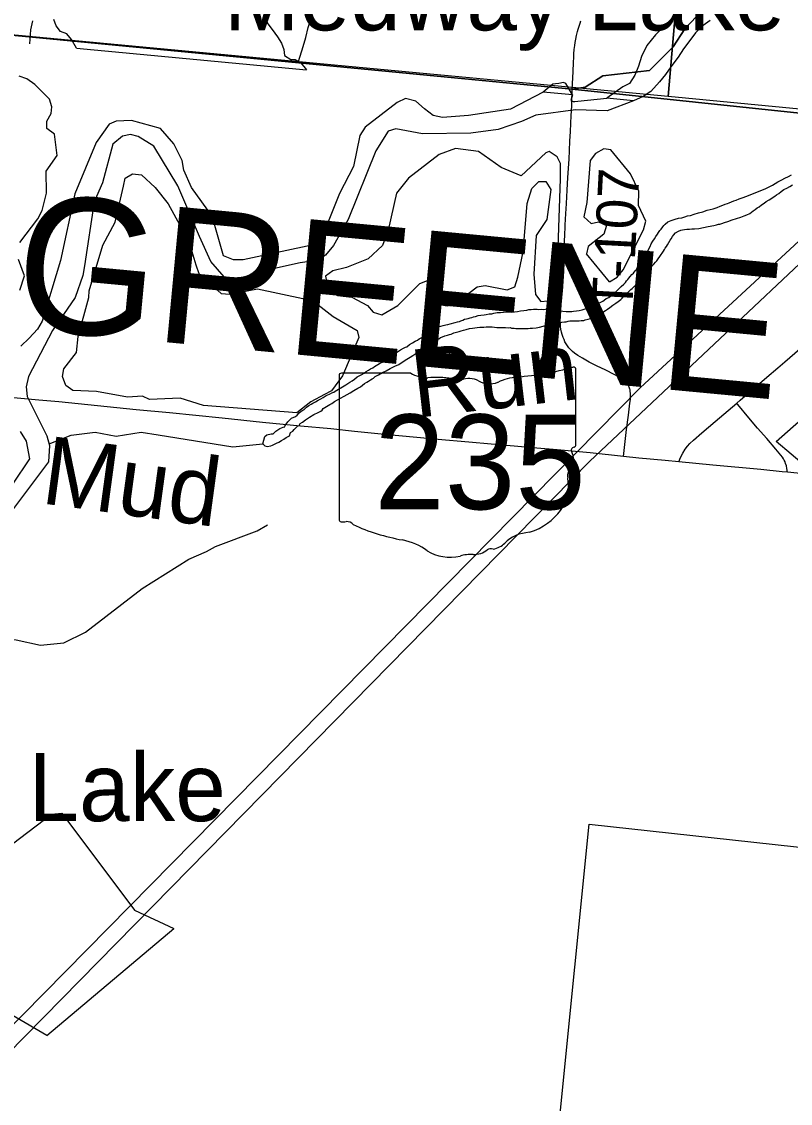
# Model space of a CAD drawing. Extents: x 0 to 1134, y 0 to 440.
# Drawn here: x 180.08 to 212.17, y 41.38 to 86.55 of the extents above; entities that cross this region are included whole.
import ezdxf

# ---------------------------------------------------------------- set-up
doc = ezdxf.new("R2010")
doc.units = 0
for name, color, linetype in [('GM_X_County_Road', 7, 'Continuous'), ('GM_X_County_Text', 7, 'Continuous'), ('GM_X_Major_River', 7, 'Continuous'), ('GM_X_Major_River_Text', 7, 'Continuous'), ('GM_X_Minor_Lake', 7, 'Continuous'), ('GM_X_Minor_Lake_Text', 7, 'Continuous'), ('GM_X_Minor_River', 7, 'Continuous'), ('GM_X_Rail_Line', 7, 'Continuous'), ('GM_X_Section', 7, 'Continuous'), ('GM_X_State_Location', 7, 'Continuous'), ('GM_X_State_Route', 7, 'Continuous'), ('GM_X_State_Shield', 7, 'Continuous'), ('GM_X_Township', 7, 'Continuous'), ('GM_X_Township_Road', 7, 'Continuous'), ('GM_X_Township_Road_Text', 7, 'Continuous'), ('GM_X_Unincorporated', 7, 'Continuous'), ('SH_Cut_Line', 7, 'Continuous')]:
    doc.layers.add(name, color=color, linetype=linetype)

msp = doc.modelspace()

# ---------------------------------------------------------------- linework, layer by layer
at = {"layer": 'GM_X_County_Road'}
msp.add_lwpolyline([(203.063, 83.709), (203.096, 84.469), (203.113, 84.838), (203.126, 85.062), (203.136, 85.208), (203.149, 85.388), (203.166, 85.548), (203.184, 85.681), (203.208, 85.815), (203.24, 85.969), (203.282, 86.14), (203.309, 86.23), (203.333, 86.318), (203.391, 86.486), (203.429, 86.579)], dxfattribs=at)
at = {"layer": 'GM_X_Major_River'}
for p, q in [((203.08, 83.489), (201.856, 83.604)), ((205.625, 83.249), (204.501, 83.355))]:
    msp.add_line(p, q, dxfattribs=at)
for points in [[(211.62, 91.109), (211.191, 90.801), (210.749, 90.459), (210.331, 90.128), (210.095, 89.826), (209.823, 89.411), (209.712, 89.095), (209.635, 88.778), (209.489, 88.383), (209.163, 88.106), (208.78, 87.831), (208.454, 87.566), (208.084, 87.324), (207.701, 87.072), (207.281, 86.672), (206.885, 86.329), (206.535, 85.996), (206.182, 85.549), (205.954, 85.088), (205.83, 84.692), (205.683, 84.32), (205.458, 83.961), (205.17, 83.832), (204.501, 83.355)], [(208.828, 86.599), (208.527, 86.39), (208.211, 86.079), (207.975, 85.766), (207.705, 85.42), (207.479, 85.072), (207.184, 84.669), (206.96, 84.345), (206.712, 84.032), (206.338, 83.631), (206.025, 83.423), (205.625, 83.249)], [(201.856, 83.604), (200.487, 82.899), (198.739, 82.627), (197.645, 82.554), (197.261, 82.632), (196.892, 82.915), (196.536, 83.231), (196.107, 83.345), (195.75, 83.173), (194.415, 82.14), (194.19, 81.793), (193.93, 80.504), (193.343, 79.371), (192.626, 77.57), (192.391, 77.258), (189.325, 76.601), (188.927, 76.6), (188.51, 76.77), (188.029, 78.432), (187.172, 79.627), (186.85, 80.352), (186.78, 80.752), (186.434, 81.444), (185.87, 82.084), (184.661, 82.424), (184.023, 82.395), (183.736, 82.267), (183.193, 81.508), (182.296, 79.36), (181.702, 76.578), (180.932, 74.04), (180.741, 73.704), (180.39, 73.326), (180.041, 72.995)], [(203.08, 83.489), (202.793, 83.971), (202.703, 84.008), (202.508, 83.967), (202.371, 83.959), (202.257, 83.94), (201.856, 83.604)], [(205.625, 83.249), (204.524, 82.825), (203.194, 82.872), (201.55, 82.643), (200.94, 82.386), (199.965, 82.048), (198.834, 81.896), (196.808, 81.859), (195.699, 82.071), (195.378, 81.977), (194.868, 81.161), (193.703, 78.292), (193.095, 77.205), (192.766, 76.793), (192.477, 76.619), (192.099, 76.538), (191.711, 76.48), (190.636, 76.247), (189.235, 75.739), (188.848, 75.738), (188.533, 75.894), (187.969, 76.535), (187.496, 77.582), (186.594, 79.688), (185.601, 81.352), (184.94, 81.757), (184.623, 81.833), (184.281, 81.774), (183.885, 81.432), (183.457, 79.818), (183.107, 79.02), (182.697, 76.347), (182.63, 75.95), (182.311, 75.026), (181.366, 73.653), (180.361, 71.735), (180.259, 71.294), (180.305, 70.895), (181.128, 69.258), (181.243, 68.856), (181.203, 68.164), (179.695, 66.168)], [(203.08, 83.489), (203.009, 83.261), (203.098, 83.213), (203.167, 83.211), (203.292, 83.231), (204.501, 83.355)], [(180.018, 69.435), (180.269, 69.031), (180.409, 68.287), (179.689, 67.238)]]:
    msp.add_lwpolyline(points, dxfattribs=at)
at = {"layer": 'GM_X_Minor_Lake'}
msp.add_line((182.362, 85.444), (191.964, 84.538), dxfattribs=at)
for points in [[(182.362, 85.444), (182.164, 85.804), (181.963, 86.046), (181.702, 86.141), (181.524, 86.382), (181.425, 86.645)], [(190.207, 86.703), (190.351, 86.462), (190.53, 86.22), (190.765, 85.921), (190.931, 85.657), (191.018, 85.394), (191.049, 85.132)], [(191.049, 85.132), (191.32, 84.968), (191.49, 84.966), (191.738, 84.826), (191.964, 84.538)], [(179.999, 77.333), (180.747, 78.319), (180.936, 78.669), (181.109, 79.382), (181.105, 80.305), (181.562, 80.967), (181.454, 81.846), (181.129, 82.092), (181.124, 82.4), (181.312, 82.715), (181.341, 82.999), (181.233, 83.309), (180.631, 83.924), (180.294, 84.159), (179.967, 84.28)], [(200.926, 80.106), (200.102, 80.453), (199.148, 81.133), (198.195, 81.255), (197.507, 81.007), (196.224, 80.02), (195.722, 79.392), (195.372, 77.839), (195.143, 77.195), (194.54, 76.649), (193.645, 76.28), (193.062, 76.144), (192.762, 75.922), (192.886, 75.316), (193.258, 75.115), (193.86, 75.046), (194.513, 74.702), (194.746, 74.413), (195.108, 74.303), (195.776, 74.699), (196.705, 75.614), (197.015, 75.745), (197.308, 75.625), (197.541, 75.313), (197.518, 74.732), (197.847, 74.68), (198.167, 74.765), (199.092, 75.475), (199.423, 75.525), (200.341, 75.347), (200.662, 75.477), (200.796, 75.884), (201.01, 76.939), (201.176, 78.951), (201.37, 79.585), (201.672, 79.875), (201.957, 79.881), (202.166, 79.546), (202.005, 78.285), (201.559, 77.623), (201.458, 76.008), (201.532, 75.152), (201.754, 74.863), (202.039, 74.891), (202.307, 75.205), (202.482, 77.126), (202.573, 79.982), (202.58, 80.301), (202.575, 80.62), (202.432, 80.907), (202.095, 81.13), (201.958, 81.065)], [(201.958, 81.065), (200.926, 80.106)], [(204.615, 75.682), (204.938, 75.88), (205.194, 76.182), (206.036, 77.851), (206.134, 78.224), (205.829, 78.868), (205.841, 79.472), (205.491, 80.196), (204.68, 81.192), (204.385, 81.243), (204.028, 81.046), (203.806, 80.754), (203.669, 78.992), (203.543, 78.402), (203.856, 78.123), (204.165, 78.185), (204.492, 78.041), (204.382, 77.679), (203.723, 77.157), (203.66, 76.851)], [(187.669, 70.514), (186.697, 70.83), (185.421, 70.765), (185.117, 70.908), (184.49, 70.875), (183.209, 71.106), (182.219, 71.149), (181.928, 71.36), (181.776, 71.728), (181.839, 72.057), (182.365, 72.729), (182.435, 73.4), (182.877, 75.03), (182.894, 75.315), (183.467, 77.216), (183.987, 78.174), (184.336, 79.681), (184.399, 80.01), (184.699, 80.197), (185.074, 80.155), (185.655, 79.62), (186.188, 78.948), (187.055, 77.371), (187.354, 76.397), (187.472, 76.03), (188.412, 75.202), (188.764, 75.172), (189.929, 75.388), (191.81, 74.985), (192.453, 74.721), (193.081, 74.23), (194.082, 73.652), (194.156, 73.366), (193.475, 71.763), (193.019, 71.134), (192.72, 70.981), (192.155, 70.667), (191.567, 70.218)], [(204.615, 75.682), (203.66, 76.851)], [(180.004, 75.34), (180.198, 75.939), (179.95, 76.616)], [(191.567, 70.218), (187.669, 70.514)], [(179.69, 52.215), (181.319, 53.458), (181.752, 53.494), (184.79, 49.446), (186.436, 48.683)], [(181.123, 44.212), (186.436, 48.683)], [(181.123, 44.212), (179.728, 45.026)]]:
    msp.add_lwpolyline(points, dxfattribs=at)
at = {"layer": 'GM_X_Minor_River'}
for points in [[(180.418, 85.628), (180.464, 86.215), (180.549, 86.59)], [(191.638, 84.883), (191.828, 85.508), (191.935, 85.882), (192.044, 86.302), (192.163, 86.698)], [(209.706, 79.023), (209.809, 79.067), (209.912, 79.1), (210.027, 79.144), (210.153, 79.199), (210.347, 79.264), (210.519, 79.329), (211.046, 79.537), (211.15, 79.581), (211.253, 79.636), (211.345, 79.68), (211.425, 79.725), (211.54, 79.791), (211.644, 79.858), (211.816, 79.946), (211.942, 80.013), (212.091, 80.079), (212.218, 80.156)], [(210.622, 78.644), (210.703, 78.711), (210.784, 78.778), (210.864, 78.822), (210.968, 78.9), (211.072, 78.967), (211.164, 79.034), (211.279, 79.112), (211.52, 79.256), (211.589, 79.312), (211.682, 79.379), (211.785, 79.457), (211.9, 79.535), (212.027, 79.601), (212.142, 79.668), (212.257, 79.734)], [(200.294, 74.425), (200.408, 74.435), (200.522, 74.421), (200.659, 74.43), (200.785, 74.451), (200.91, 74.472), (201.036, 74.481), (201.161, 74.502), (201.253, 74.523), (201.344, 74.533), (201.447, 74.543), (201.538, 74.542), (201.606, 74.54), (201.674, 74.528), (201.765, 74.538), (201.879, 74.536), (201.948, 74.546), (202.039, 74.556), (202.096, 74.555), (202.187, 74.542), (202.255, 74.541), (202.312, 74.529), (202.38, 74.517), (202.437, 74.504), (202.516, 74.469), (202.675, 74.455), (202.812, 74.441), (202.948, 74.45), (203.051, 74.449), (203.119, 74.459), (203.245, 74.468), (203.348, 74.489), (203.473, 74.522), (203.599, 74.554), (203.737, 74.609), (203.84, 74.652), (203.92, 74.685), (203.989, 74.718), (204.115, 74.785), (204.172, 74.795), (204.253, 74.839), (204.345, 74.884), (204.402, 74.917), (204.483, 74.984), (204.586, 75.028), (204.678, 75.095), (204.759, 75.15), (204.84, 75.229), (204.921, 75.307), (205.002, 75.397), (205.106, 75.486), (205.221, 75.587), (205.291, 75.654), (205.326, 75.722), (205.384, 75.778), (205.43, 75.834), (205.488, 75.902), (205.558, 75.992), (205.616, 76.048), (205.686, 76.138), (205.744, 76.205), (205.86, 76.374), (205.919, 76.487), (206, 76.577), (206.047, 76.667), (206.105, 76.769), (206.164, 76.859), (206.199, 76.938), (206.246, 77.04), (206.317, 77.164), (206.364, 77.277), (206.423, 77.379), (206.493, 77.48), (206.551, 77.571), (206.621, 77.672), (206.668, 77.751), (206.726, 77.83), (206.772, 77.886), (206.842, 77.976), (206.888, 78.032), (206.946, 78.088), (207.05, 78.189), (207.199, 78.244), (207.36, 78.298), (207.497, 78.341), (207.634, 78.362), (207.76, 78.394), (207.874, 78.438), (208, 78.459), (208.16, 78.513), (208.332, 78.567), (208.515, 78.61), (208.698, 78.675), (208.95, 78.739), (209.11, 78.794), (209.236, 78.849), (209.35, 78.881), (209.454, 78.925), (209.545, 78.958), (209.614, 78.979), (209.706, 79.023)], [(200.705, 73.735), (200.83, 73.733), (200.978, 73.742), (201.092, 73.729), (201.217, 73.738), (201.309, 73.748), (201.4, 73.746), (201.56, 73.766), (201.697, 73.787), (201.845, 73.83), (201.983, 73.874), (202.131, 73.905), (202.28, 73.937), (202.417, 73.969), (202.531, 73.979), (202.634, 74), (202.737, 74.021), (202.805, 74.02), (202.896, 74.041), (202.965, 74.051), (203.022, 74.062), (203.352, 74.056), (203.432, 74.067), (203.546, 74.076), (203.603, 74.098), (203.729, 74.119), (203.821, 74.151), (203.878, 74.162), (203.958, 74.195), (204.039, 74.25), (204.165, 74.305), (204.245, 74.361), (204.337, 74.416), (204.452, 74.483), (204.533, 74.55), (204.637, 74.617), (204.763, 74.706), (204.89, 74.795), (204.982, 74.862), (205.086, 74.94), (205.167, 75.018), (205.225, 75.108), (205.294, 75.164), (205.352, 75.209), (205.41, 75.265), (205.514, 75.366), (205.572, 75.41), (205.653, 75.489), (205.745, 75.567), (205.815, 75.657), (205.85, 75.714), (205.896, 75.77), (205.931, 75.838), (206.001, 75.916), (206.07, 75.983), (206.175, 76.096), (206.233, 76.174), (206.303, 76.264), (206.383, 76.343), (206.464, 76.421), (206.545, 76.5), (206.592, 76.567), (206.65, 76.646), (206.72, 76.736), (206.872, 76.962), (206.918, 77.041), (206.942, 77.097), (207, 77.165), (207.047, 77.232), (207.094, 77.323), (207.152, 77.424), (207.187, 77.481), (207.246, 77.582), (207.292, 77.638), (207.373, 77.728), (207.5, 77.806), (207.592, 77.839), (207.672, 77.86), (207.751, 77.87), (207.854, 77.88), (207.957, 77.89), (208.059, 77.899), (208.173, 77.898), (208.344, 77.918), (208.538, 77.949), (208.733, 77.991), (208.973, 78.044), (209.087, 78.065), (209.167, 78.087), (209.224, 78.086), (209.304, 78.119), (209.419, 78.162), (209.556, 78.206), (209.739, 78.271), (209.923, 78.336), (210.106, 78.39), (210.243, 78.434), (210.358, 78.477), (210.472, 78.533), (210.542, 78.6), (210.622, 78.644)], [(190.14, 68.916), (190.236, 69.222), (190.317, 69.301), (190.488, 69.332), (190.579, 69.342), (190.695, 69.454), (190.856, 69.565), (190.994, 69.62), (191.062, 69.63), (191.074, 69.687), (191.191, 69.833), (191.341, 69.99), (191.513, 70.067), (191.582, 70.123), (191.664, 70.213), (191.744, 70.28), (191.813, 70.324), (191.871, 70.358), (191.963, 70.447), (192.067, 70.514), (192.159, 70.57), (192.228, 70.614), (192.343, 70.68), (192.458, 70.747), (192.561, 70.802), (192.665, 70.858), (192.791, 70.935), (192.929, 70.99), (193.021, 71.045), (193.112, 71.078), (193.17, 71.123), (193.239, 71.167), (193.538, 71.345), (193.607, 71.378), (193.699, 71.445), (193.779, 71.5), (193.871, 71.556), (193.975, 71.622), (194.09, 71.712), (194.274, 71.811), (194.377, 71.866), (194.458, 71.934), (194.562, 71.989), (194.642, 72.056), (194.734, 72.1), (194.815, 72.144), (194.884, 72.189), (195.01, 72.278), (195.125, 72.333), (195.194, 72.389), (195.298, 72.433), (195.39, 72.488), (195.482, 72.566), (195.586, 72.644), (195.724, 72.733), (195.896, 72.844), (196.023, 72.911), (196.103, 72.955), (196.16, 72.977), (196.276, 73.066), (196.39, 73.133), (196.506, 73.21), (196.597, 73.255), (196.678, 73.299), (196.758, 73.343), (196.838, 73.376), (196.919, 73.454), (197, 73.521), (197.081, 73.589), (197.184, 73.644), (197.288, 73.699), (197.391, 73.754), (197.472, 73.799), (197.575, 73.831), (197.678, 73.864), (197.78, 73.885), (197.872, 73.906), (197.963, 73.927), (198.18, 73.981), (198.272, 74.014), (198.352, 74.035), (198.409, 74.057), (198.49, 74.09), (198.57, 74.123), (198.65, 74.133), (198.719, 74.154), (198.799, 74.187), (198.867, 74.198), (198.936, 74.219), (199.027, 74.24), (199.13, 74.273), (199.245, 74.294), (199.381, 74.303), (199.473, 74.324), (199.598, 74.345), (199.701, 74.355), (199.793, 74.376), (199.93, 74.397), (200.066, 74.406), (200.192, 74.415), (200.294, 74.425)], [(190.151, 68.916), (190.14, 68.916), (190.23, 68.835), (190.332, 68.81), (190.48, 68.842), (190.549, 68.864), (190.606, 68.886), (190.71, 68.941), (190.813, 68.985), (190.928, 69.063), (191.02, 69.118), (191.123, 69.185), (191.204, 69.229), (191.261, 69.251), (191.297, 69.387), (191.401, 69.454), (191.459, 69.521), (191.598, 69.656), (191.667, 69.689), (191.702, 69.768), (191.805, 69.823), (191.932, 69.924), (192.094, 70.035), (192.278, 70.146), (192.461, 70.234), (192.564, 70.278), (192.622, 70.323), (192.669, 70.39), (192.807, 70.479), (192.945, 70.557), (193.025, 70.601), (193.14, 70.69), (193.795, 71.056), (193.945, 71.144), (194.106, 71.244), (194.22, 71.299), (194.301, 71.366), (194.393, 71.433), (194.485, 71.489), (194.554, 71.533), (194.635, 71.589), (194.704, 71.633), (194.773, 71.666), (194.842, 71.734), (194.98, 71.8), (195.141, 71.9), (195.29, 71.966), (195.463, 72.065), (195.658, 72.165), (195.818, 72.23), (195.968, 72.331), (196.152, 72.453), (196.301, 72.542), (196.405, 72.608), (196.497, 72.664), (196.566, 72.708), (196.682, 72.82), (196.774, 72.887), (196.854, 72.943), (196.935, 72.987), (197.015, 73.031), (197.084, 73.064), (197.153, 73.12), (197.257, 73.175), (197.314, 73.186), (197.406, 73.264), (197.487, 73.308), (197.567, 73.353), (197.647, 73.386), (197.739, 73.43), (197.853, 73.462), (197.933, 73.484), (198.014, 73.505), (198.117, 73.549), (198.231, 73.581), (198.346, 73.614), (198.426, 73.635), (198.529, 73.668), (198.631, 73.689), (198.78, 73.732), (198.906, 73.753), (198.997, 73.762), (199.088, 73.772), (199.203, 73.793), (199.373, 73.791), (199.476, 73.8), (199.533, 73.799), (199.624, 73.809), (199.727, 73.808), (199.818, 73.795), (199.92, 73.782), (200.011, 73.78), (200.102, 73.779), (200.193, 73.777), (200.273, 73.776), (200.386, 73.763), (200.466, 73.773), (200.523, 73.749), (200.58, 73.748), (200.637, 73.747), (200.705, 73.735)], [(181.225, 68.919), (182.148, 69.283), (183.141, 69.411), (184.025, 69.245), (185.064, 69.406), (185.779, 69.3), (188.898, 68.792), (190.14, 68.916)], [(173.158, 59.748), (173.658, 59.594), (174.534, 59.03), (175.145, 58.835), (175.773, 58.97), (176.419, 59.39), (177.015, 59.605), (177.697, 60.126), (178.035, 60.495), (178.644, 60.79), (179.849, 60.732), (180.868, 60.506), (181.838, 60.611), (182.746, 61.06), (185.115, 62.879), (187.063, 64.104), (187.798, 64.419), (188.177, 64.627), (189.909, 65.287), (190.347, 65.54)]]:
    msp.add_lwpolyline(points, dxfattribs=at)
at = {"layer": 'GM_X_Rail_Line'}
for points in [[(151.357, 17.107), (165.007, 29.729), (205.893, 71.252), (217.865, 82.321)], [(153.633, 17.107), (203.787, 68.18), (218.71, 82.241)], [(204.659, 17.107), (213.552, 20.586), (215.209, 21.415), (216.984, 36.987), (218.344, 50.421), (218.813, 57.67), (218.896, 60.013), (218.144, 62.355), (214.715, 66.37), (211.574, 69.017), (218.175, 74.838), (219.935, 76.648), (222.429, 78.605)]]:
    msp.add_lwpolyline(points, dxfattribs=at)
at = {"layer": 'GM_X_Section'}
for points in [[(209.686, 113.866), (207.062, 83.429), (175.637, 86.374), (175.645, 86.452), (178.478, 116.514)], [(239.744, 111.129), (236.861, 80.551), (207.062, 83.429), (209.686, 113.866)], [(233.815, 49.749), (230.856, 19.956), (200.744, 22.898), (203.767, 53.031)]]:
    msp.add_lwpolyline(points, close=True, dxfattribs=at)
at = {"layer": 'GM_X_State_Route'}
for points in [[(198.427, 69.011), (197.774, 69.067), (195.231, 69.311), (193.97, 69.44), (192.988, 69.54), (191.725, 69.658), (190.13, 69.817), (188.443, 69.989), (186.254, 70.208), (184.862, 70.34), (181.635, 70.668), (180.8, 70.742), (179.89, 70.823), (179.222, 70.892), (178.87, 70.928), (178.017, 71.018), (177.424, 71.082), (176.534, 71.171), (175.53, 71.273), (175.06, 71.319), (174.212, 71.383)], [(212.713, 67.663), (212.05, 67.731), (211.823, 67.754), (210.933, 67.847), (208.928, 68.034), (207.508, 68.17), (206.943, 68.224), (205.848, 68.327), (205.208, 68.393), (203.808, 68.537), (202.435, 68.668), (201.582, 68.745), (200.002, 68.874), (198.427, 69.011)]]:
    msp.add_lwpolyline(points, dxfattribs=at)
at = {"layer": 'GM_X_State_Shield'}
for p, q in [((196.323, 71.871), (193.427, 71.871)), ((203.218, 68.879), (203.218, 72.02)), ((193.33, 71.768), (193.33, 65.764)), ((203.217, 68.88), (203.218, 68.879))]:
    msp.add_line(p, q, dxfattribs=at)
for centre, major_axis, start_param, end_param in [((193.443, 71.781), (0.115, 0), 1.712693, 3.28349), ((197.013, 72.568), (1.111, 0), 4.042523, 4.731795), ((199.696, 80.056), (10.486, 0), 4.814394, 5.042369), ((203.108, 72.033), (0.11, 0), 6.141152, 7.989035), ((197.381, 68.501), (3.989, 0), 1.404758, 1.657858), ((198.287, 71.812), (0.321, 0), 3.836095, 5.185415), ((198.757, 71.118), (0.666, 0), 0.950623, 2.079405), ((199.617, 72.07), (0.802, 0), 4.081561, 5.145723), ((201.033, 70.037), (2.11, 0), 1.699011, 2.107814), ((203.192, 68.649), (0.17, 0), 1.883978, 3.671073), ((203.1, 68.867), (0.118, 0), 5.05454, 6.418171), ((202.108, 68.252), (1.023, 0), 5.934695, 6.695948), ((203.612, 67.565), (0.744, 0), 2.387724, 3.262537), ((200.283, 67.166), (2.623, 0), 5.101752, 6.440018), ((193.444, 65.751), (0.116, 0), 3.00124, 4.508301), ((193.462, 66.365), (0.882, 0), 4.665946, 4.897461), ((193.642, 65.418), (0.318, 0), 0.519207, 1.627899), ((197.657, 70.812), (7.572, 0), 4.195997, 4.488961), ((201.389, 64.079), (1.436, 0), 1.647645, 2.488434), ((195.4, 63.067), (2.369, 0), 0.823519, 1.323587), ((199.569, 65.182), (0.847, 0), 4.937069, 5.64225), ((197.962, 65.388), (1.503, 0), 4.026481, 4.996735), ((198.831, 63.312), (1.235, 0), 1.495662, 1.94098), ((198.94, 64.939), (0.801, 0), 4.691044, 5.507374), ((199.665, 64.357), (0.226, 0), 1.147584, 2.315152)]:
    msp.add_ellipse(centre, major_axis=major_axis, ratio=0.8, start_param=start_param, end_param=end_param, dxfattribs=at)
at = {"layer": 'GM_X_Township'}
for points in [[(208.481, 87.014), (207.765, 86.254), (207.274, 85.494), (206.29, 84.511), (204.339, 84.291), (203.598, 83.809), (203.056, 83.725), (175.597, 86.381), (176.426, 95.74)], [(335.783, 70.994), (282.056, 76.051), (277.938, 76.439), (271.82, 77.017), (271.49, 77.048), (270.873, 77.107), (270.427, 77.153), (267.348, 77.44), (223.396, 81.589), (203.056, 83.725), (203.598, 83.809), (204.339, 84.291), (206.29, 84.511), (207.274, 85.494), (207.765, 86.254), (208.481, 87.014)]]:
    msp.add_lwpolyline(points, dxfattribs=at)
at = {"layer": 'GM_X_Township_Road'}
for points in [[(202.929, 80.822), (202.948, 81.151), (202.967, 81.575), (202.988, 81.946), (203.004, 82.306), (203.021, 82.62), (203.031, 82.831), (203.041, 83.034), (203.044, 83.154), (203.063, 83.709)], [(202.765, 77.949), (202.77, 78.061), (202.784, 78.288), (202.797, 78.532), (202.807, 78.729), (202.817, 78.95), (202.851, 79.514), (202.884, 80.045), (202.917, 80.613), (202.929, 80.822)], [(205.208, 68.393), (205.266, 68.886), (205.332, 69.524), (205.409, 70.114), (205.474, 70.611), (205.489, 70.77), (205.496, 70.906), (205.495, 71.016), (205.486, 71.123), (205.478, 71.174), (205.468, 71.206), (205.439, 71.287), (205.412, 71.348), (205.386, 71.398), (205.359, 71.438), (205.326, 71.481), (205.296, 71.518), (205.232, 71.575), (205.152, 71.635), (205.045, 71.698), (204.955, 71.745), (204.848, 71.802), (204.437, 72.004), (204.1, 72.165), (203.767, 72.335), (203.489, 72.497), (203.298, 72.609), (203.162, 72.711), (203.081, 72.777), (203.005, 72.847), (202.926, 72.93), (202.861, 73.014), (202.811, 73.091), (202.76, 73.181), (202.721, 73.273), (202.684, 73.355), (202.64, 73.488), (202.616, 73.577), (202.589, 73.706), (202.573, 73.823), (202.567, 73.926), (202.565, 74.026), (202.583, 74.477), (202.613, 75.055), (202.657, 75.843), (202.707, 76.819), (202.734, 77.323), (202.754, 77.7), (202.764, 77.921), (202.765, 77.949)], [(209.928, 70.622), (210.075, 70.748), (211.19, 71.709), (211.644, 72.096), (211.942, 72.35), (212.986, 73.253)], [(207.508, 68.17), (207.589, 68.345), (207.677, 68.534), (207.774, 68.696), (207.872, 68.824), (207.97, 68.932), (208.121, 69.074), (208.475, 69.377), (209.027, 69.85), (209.928, 70.622)], [(212.05, 67.731), (212.022, 67.883), (212.002, 67.994), (211.971, 68.102), (211.948, 68.173), (211.914, 68.237), (211.877, 68.298), (211.836, 68.359), (211.701, 68.531), (211.56, 68.701), (211.182, 69.145), (210.804, 69.573), (210.432, 70.008), (209.981, 70.558), (209.928, 70.622)]]:
    msp.add_lwpolyline(points, dxfattribs=at)
at = {"layer": 'GM_X_Unincorporated'}
msp.add_lwpolyline([(223.396, 81.589), (203.056, 83.725), (175.597, 86.381)], dxfattribs=at)
at = {"layer": 'SH_Cut_Line'}
for points in [[(191.505, 262.177), (186.299, 206.946), (186.171, 205.401), (184.337, 184.605), (184.291, 183.936), (180.952, 146.735), (180.65, 140.913), (178.666, 119.298), (178.473, 116.876), (178.429, 116.408), (178.401, 116.166), (178.274, 114.839), (176.426, 95.74), (175.597, 86.381), (203.056, 83.725), (223.396, 81.589), (267.348, 77.44), (270.427, 77.153), (270.873, 77.107), (271.49, 77.048), (271.82, 77.017), (277.938, 76.439), (282.056, 76.051), (335.783, 70.994)], [(223.396, 81.589), (203.056, 83.725), (175.597, 86.381)]]:
    msp.add_lwpolyline(points, dxfattribs=at)

# ---------------------------------------------------------------- texts
at = {"layer": 'GM_X_County_Text'}
msp.add_text('GREENE COUNTY', height=5.68182, rotation=354.6158, dxfattribs=at).set_placement((179.644, 73.772))
at = {"layer": 'GM_X_Major_River_Text'}
for s, height, rotation, p in [('Run', 2.8408, 6.5531, (196.514, 70.002)), ('Mud', 2.8409, 352.2552, (180.836, 66.443))]:
    msp.add_text(s, height=height, rotation=rotation, dxfattribs=at).set_placement(p)
at = {"layer": 'GM_X_Minor_Lake_Text'}
for s, height, rotation, p in [('Medway Lake', 2.84082, 0.0032, (188.515, 86.187)), ('Bass Lake', 2.8408, 359.9946, (170.863, 53.163))]:
    msp.add_text(s, height=height, rotation=rotation, dxfattribs=at).set_placement(p)
at = {"layer": 'GM_X_State_Location'}
for s in ['s', 'r']:
    msp.add_text(s, height=0.00568, dxfattribs=at).set_placement((198.163, 68.367))
msp.add_text('235', height=0.00568, rotation=0, dxfattribs=at).set_placement((196.157, 67.954))
at = {"layer": 'GM_X_State_Shield'}
msp.add_text('235', height=3.9551, dxfattribs=at).set_placement((194.804, 66.188))
at = {"layer": 'GM_X_Township_Road_Text'}
msp.add_text('T-107', height=1.7045, rotation=86.9468, dxfattribs=at).set_placement((205.562, 74.428))

doc.saveas('drawing.dxf')
